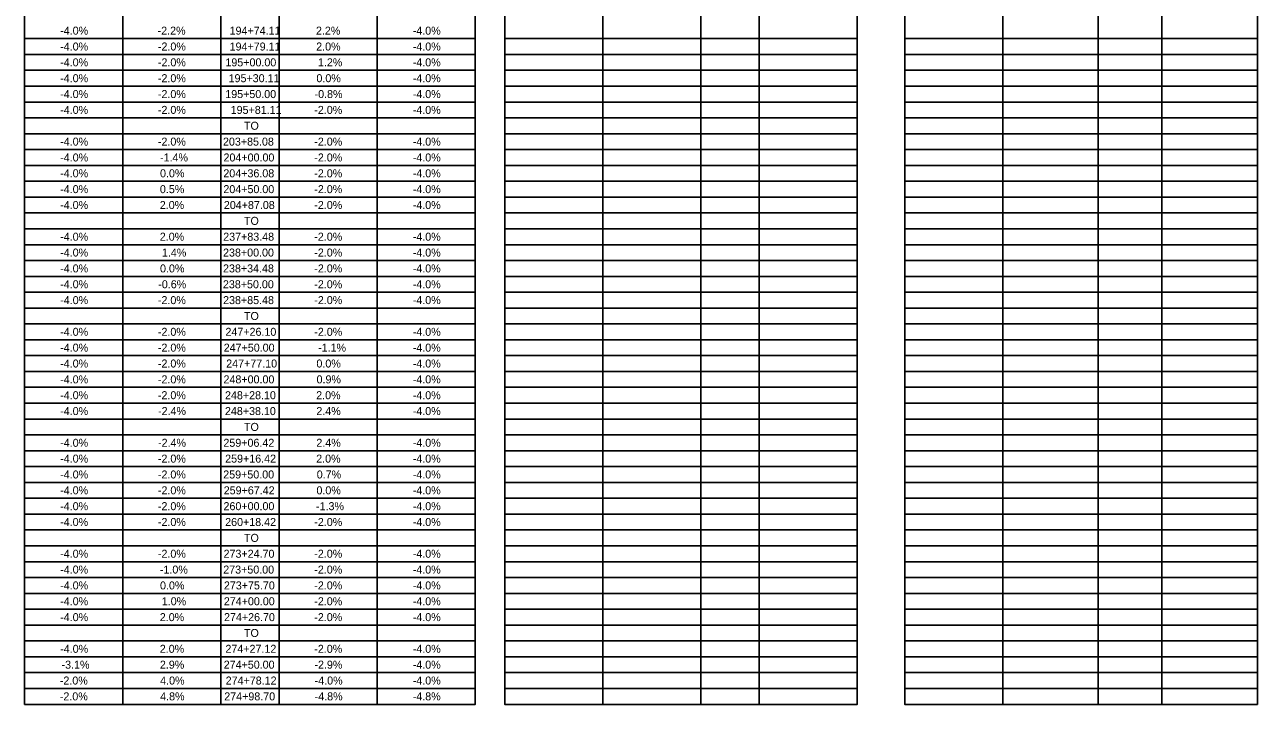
# Model space of a CAD drawing. Extents: x -15319374 to 1762012, y 465773 to 3693661.
# Drawn here: x -15317075.3 to -15316613.1, y 3692508 to 3692762.8 of the extents above; entities that cross this region are included whole.
import ezdxf

# ---------------------------------------------------------------- set-up
doc = ezdxf.new("R2010")
doc.units = 0
doc.layers.add('BORDER', color=7, linetype='Continuous')
doc.layers.add('DIMENSIONS', color=7, linetype='Continuous')

msp = doc.modelspace()

# ---------------------------------------------------------------- linework, layer by layer
at = {"layer": 'BORDER'}
for p, q in [((-15317038.55, 3693013.06), (-15317038.55, 3692507.99)), ((-15317001.78, 3693013.06), (-15317001.78, 3692507.99)), ((-15316979.91, 3693013.06), (-15316979.91, 3692507.99)), ((-15316943.14, 3693013.06), (-15316943.14, 3692507.99)), ((-15316858.55, 3693013.06), (-15316858.55, 3692507.99)), ((-15316821.78, 3693013.06), (-15316821.78, 3692507.99)), ((-15316799.91, 3693013.06), (-15316799.91, 3692507.99)), ((-15316708.55, 3693013.06), (-15316708.55, 3692507.99)), ((-15316672.78, 3693013.06), (-15316672.78, 3692507.99)), ((-15316648.91, 3693013.06), (-15316648.91, 3692507.99)), ((-15317075.32, 3692757.59), (-15316906.37, 3692757.59)), ((-15316895.32, 3692757.59), (-15316763.14, 3692757.59)), ((-15316745.32, 3692757.59), (-15316613.14, 3692757.59)), ((-15317075.32, 3692751.64), (-15316906.37, 3692751.64)), ((-15316895.32, 3692751.64), (-15316763.14, 3692751.64)), ((-15316745.32, 3692751.64), (-15316613.14, 3692751.64)), ((-15317075.32, 3692745.7), (-15316906.37, 3692745.7)), ((-15316895.32, 3692745.7), (-15316763.14, 3692745.7)), ((-15316745.32, 3692745.7), (-15316613.14, 3692745.7)), ((-15317075.32, 3692739.76), (-15316906.37, 3692739.76)), ((-15316895.32, 3692739.76), (-15316763.14, 3692739.76)), ((-15316745.32, 3692739.76), (-15316613.14, 3692739.76)), ((-15317075.32, 3692733.82), (-15316906.37, 3692733.82)), ((-15316895.32, 3692733.82), (-15316763.14, 3692733.82)), ((-15316745.32, 3692733.82), (-15316613.14, 3692733.82)), ((-15317075.32, 3692727.87), (-15316906.37, 3692727.87)), ((-15316895.32, 3692727.87), (-15316763.14, 3692727.87)), ((-15316745.32, 3692727.87), (-15316613.14, 3692727.87)), ((-15317075.32, 3692721.93), (-15316906.37, 3692721.93)), ((-15316895.32, 3692721.93), (-15316763.14, 3692721.93)), ((-15316745.32, 3692721.93), (-15316613.14, 3692721.93)), ((-15317075.32, 3692715.99), (-15316906.37, 3692715.99)), ((-15316895.32, 3692715.99), (-15316763.14, 3692715.99)), ((-15316745.32, 3692715.99), (-15316613.14, 3692715.99)), ((-15317075.32, 3692710.04), (-15316906.37, 3692710.04)), ((-15316895.32, 3692710.04), (-15316763.14, 3692710.04)), ((-15316745.32, 3692710.04), (-15316613.14, 3692710.04)), ((-15317075.32, 3692704.1), (-15316906.37, 3692704.1)), ((-15316895.32, 3692704.1), (-15316763.14, 3692704.1)), ((-15316745.32, 3692704.1), (-15316613.14, 3692704.1)), ((-15317075.32, 3692698.16), (-15316906.37, 3692698.16)), ((-15316895.32, 3692698.16), (-15316763.14, 3692698.16)), ((-15316745.32, 3692698.16), (-15316613.14, 3692698.16)), ((-15317075.32, 3692692.22), (-15316906.37, 3692692.22)), ((-15316895.32, 3692692.22), (-15316763.14, 3692692.22)), ((-15316745.32, 3692692.22), (-15316613.14, 3692692.22)), ((-15317075.32, 3692686.27), (-15316906.37, 3692686.27)), ((-15316895.32, 3692686.27), (-15316763.14, 3692686.27)), ((-15316745.32, 3692686.27), (-15316613.14, 3692686.27)), ((-15317075.32, 3692680.33), (-15316906.37, 3692680.33)), ((-15316895.32, 3692680.33), (-15316763.14, 3692680.33)), ((-15316745.32, 3692680.33), (-15316613.14, 3692680.33)), ((-15317075.32, 3692674.39), (-15316906.37, 3692674.39)), ((-15316895.32, 3692674.39), (-15316763.14, 3692674.39)), ((-15316745.32, 3692674.39), (-15316613.14, 3692674.39)), ((-15317075.32, 3692668.45), (-15316906.37, 3692668.45)), ((-15316895.32, 3692668.45), (-15316763.14, 3692668.45)), ((-15316745.32, 3692668.45), (-15316613.14, 3692668.45)), ((-15317075.32, 3692662.5), (-15316906.37, 3692662.5)), ((-15316895.32, 3692662.5), (-15316763.14, 3692662.5)), ((-15316745.32, 3692662.5), (-15316613.14, 3692662.5)), ((-15317075.32, 3692656.56), (-15316906.37, 3692656.56)), ((-15316895.32, 3692656.56), (-15316763.14, 3692656.56)), ((-15316745.32, 3692656.56), (-15316613.14, 3692656.56)), ((-15317075.32, 3692650.62), (-15316906.37, 3692650.62)), ((-15316895.32, 3692650.62), (-15316763.14, 3692650.62)), ((-15316745.32, 3692650.62), (-15316613.14, 3692650.62)), ((-15317075.32, 3692644.67), (-15316906.37, 3692644.67)), ((-15316895.32, 3692644.67), (-15316763.14, 3692644.67)), ((-15316745.32, 3692644.67), (-15316613.14, 3692644.67)), ((-15317075.32, 3692638.73), (-15316906.37, 3692638.73)), ((-15316895.32, 3692638.73), (-15316763.14, 3692638.73)), ((-15316745.32, 3692638.73), (-15316613.14, 3692638.73)), ((-15317075.32, 3692632.79), (-15316906.37, 3692632.79)), ((-15316895.32, 3692632.79), (-15316763.14, 3692632.79)), ((-15316745.32, 3692632.79), (-15316613.14, 3692632.79)), ((-15317075.32, 3692626.85), (-15316906.37, 3692626.85)), ((-15316895.32, 3692626.85), (-15316763.14, 3692626.85)), ((-15316745.32, 3692626.85), (-15316613.14, 3692626.85)), ((-15317075.32, 3692620.9), (-15316906.37, 3692620.9)), ((-15316895.32, 3692620.9), (-15316763.14, 3692620.9)), ((-15316745.32, 3692620.9), (-15316613.14, 3692620.9)), ((-15317075.32, 3692614.96), (-15316906.37, 3692614.96)), ((-15316895.32, 3692614.96), (-15316763.14, 3692614.96)), ((-15316745.32, 3692614.96), (-15316613.14, 3692614.96)), ((-15317075.32, 3692609.02), (-15316906.37, 3692609.02)), ((-15316895.32, 3692609.02), (-15316763.14, 3692609.02)), ((-15316745.32, 3692609.02), (-15316613.14, 3692609.02)), ((-15317075.32, 3692603.08), (-15316906.37, 3692603.08)), ((-15316895.32, 3692603.08), (-15316763.14, 3692603.08)), ((-15316745.32, 3692603.08), (-15316613.14, 3692603.08)), ((-15317075.32, 3692597.13), (-15316906.37, 3692597.13)), ((-15316895.32, 3692597.13), (-15316763.14, 3692597.13)), ((-15316745.32, 3692597.13), (-15316613.14, 3692597.13)), ((-15317075.32, 3692591.19), (-15316906.37, 3692591.19)), ((-15316895.32, 3692591.19), (-15316763.14, 3692591.19)), ((-15316745.32, 3692591.19), (-15316613.14, 3692591.19)), ((-15317075.32, 3692585.25), (-15316906.37, 3692585.25)), ((-15316895.32, 3692585.25), (-15316763.14, 3692585.25)), ((-15316745.32, 3692585.25), (-15316613.14, 3692585.25)), ((-15317075.32, 3692579.31), (-15316906.37, 3692579.31)), ((-15316895.32, 3692579.31), (-15316763.14, 3692579.31)), ((-15316745.32, 3692579.31), (-15316613.14, 3692579.31)), ((-15317075.32, 3692573.36), (-15316906.37, 3692573.36)), ((-15316895.32, 3692573.36), (-15316763.14, 3692573.36)), ((-15316745.32, 3692573.36), (-15316613.14, 3692573.36)), ((-15317075.32, 3692567.42), (-15316906.37, 3692567.42)), ((-15316895.32, 3692567.42), (-15316763.14, 3692567.42)), ((-15316745.32, 3692567.42), (-15316613.14, 3692567.42)), ((-15317075.32, 3692561.48), (-15316906.37, 3692561.48)), ((-15316895.32, 3692561.48), (-15316763.14, 3692561.48)), ((-15316745.32, 3692561.48), (-15316613.14, 3692561.48)), ((-15317075.32, 3692555.53), (-15316906.37, 3692555.53)), ((-15316895.32, 3692555.53), (-15316763.14, 3692555.53)), ((-15316745.32, 3692555.53), (-15316613.14, 3692555.53)), ((-15317075.32, 3692549.59), (-15316906.37, 3692549.59)), ((-15316895.32, 3692549.59), (-15316763.14, 3692549.59)), ((-15316745.32, 3692549.59), (-15316613.14, 3692549.59)), ((-15317075.32, 3692543.65), (-15316906.37, 3692543.65)), ((-15316895.32, 3692543.65), (-15316763.14, 3692543.65)), ((-15316745.32, 3692543.65), (-15316613.14, 3692543.65)), ((-15317075.32, 3692537.71), (-15316906.37, 3692537.71)), ((-15316895.32, 3692537.71), (-15316763.14, 3692537.71)), ((-15316745.32, 3692537.71), (-15316613.14, 3692537.71)), ((-15317075.32, 3692531.76), (-15316906.37, 3692531.76)), ((-15316895.32, 3692531.76), (-15316763.14, 3692531.76)), ((-15316745.32, 3692531.76), (-15316613.14, 3692531.76)), ((-15317075.32, 3692525.82), (-15316906.37, 3692525.82)), ((-15316895.32, 3692525.82), (-15316763.14, 3692525.82)), ((-15316745.32, 3692525.82), (-15316613.14, 3692525.82)), ((-15317075.32, 3692519.88), (-15316906.37, 3692519.88)), ((-15316895.32, 3692519.88), (-15316763.14, 3692519.88)), ((-15316745.32, 3692519.88), (-15316613.14, 3692519.88)), ((-15317075.32, 3692513.94), (-15316906.37, 3692513.94)), ((-15316895.32, 3692513.94), (-15316763.14, 3692513.94)), ((-15316745.32, 3692513.94), (-15316613.14, 3692513.94)), ((-15317075.32, 3692507.99), (-15316906.37, 3692507.99)), ((-15316745.32, 3692507.99), (-15316613.14, 3692507.99))]:
    msp.add_line(p, q, dxfattribs=at)
for points in [[(-15317075.32, 3693013.06), (-15316906.37, 3693013.06), (-15316906.37, 3692507.99), (-15317075.32, 3692507.99)], [(-15316895.32, 3693013.06), (-15316763.14, 3693013.06), (-15316763.14, 3692507.99), (-15316895.32, 3692507.99)], [(-15316745.32, 3693013.06), (-15316613.14, 3693013.06), (-15316613.14, 3692507.99), (-15316745.32, 3692507.99)]]:
    msp.add_lwpolyline(points, close=True, dxfattribs=at)
msp.add_lwpolyline([(-15317075.32, 3692507.99), (-15317075.32, 3693007.15), (-15316906.37, 3693007.15), (-15316906.37, 3692507.99)], dxfattribs=at)

# ---------------------------------------------------------------- texts
at = {"layer": 'DIMENSIONS'}
for s, p in [('-4.0%', (-15317061.99, 3692759.07)), ('-2.2%', (-15317025.46, 3692759.07)), ('194+74.11', (-15316998.47, 3692759.07)), ('2.2%', (-15316966.1, 3692759.07)), ('-4.0%', (-15316929.81, 3692759.07)), ('-4.0%', (-15317061.99, 3692753.13)), ('-2.0%', (-15317025.36, 3692753.13)), ('194+79.11', (-15316998.47, 3692753.13)), ('2.0%', (-15316966.01, 3692753.13)), ('-4.0%', (-15316929.81, 3692753.13)), ('-4.0%', (-15317061.99, 3692747.19)), ('-2.0%', (-15317025.36, 3692747.19)), ('195+00.00', (-15317000.05, 3692747.19)), ('1.2%', (-15316965.35, 3692747.19)), ('-4.0%', (-15316929.81, 3692747.19)), ('-4.0%', (-15317061.99, 3692741.25)), ('-2.0%', (-15317025.36, 3692741.25)), ('195+30.11', (-15316998.85, 3692741.25)), ('0.0%', (-15316965.92, 3692741.25)), ('-4.0%', (-15316929.81, 3692741.25)), ('-4.0%', (-15317061.99, 3692735.3)), ('-2.0%', (-15317025.36, 3692735.3)), ('195+50.00', (-15317000.1, 3692735.3)), ('-0.8%', (-15316966.62, 3692735.3)), ('-4.0%', (-15316929.81, 3692735.3)), ('-4.0%', (-15317061.99, 3692729.36)), ('-2.0%', (-15317025.36, 3692729.36)), ('195+81.11', (-15316998.07, 3692729.36)), ('-2.0%', (-15316966.72, 3692729.36)), ('-4.0%', (-15316929.81, 3692729.36)), ('TO', (-15316993.09, 3692723.42)), ('-4.0%', (-15317061.99, 3692717.47)), ('-2.0%', (-15317025.36, 3692717.47)), ('203+85.08', (-15317000.96, 3692717.47)), ('-2.0%', (-15316966.72, 3692717.47)), ('-4.0%', (-15316929.81, 3692717.47)), ('-4.0%', (-15317061.99, 3692711.53)), ('-1.4%', (-15317024.56, 3692711.53)), ('204+00.00', (-15317000.76, 3692711.53)), ('-2.0%', (-15316966.72, 3692711.53)), ('-4.0%', (-15316929.81, 3692711.53)), ('-4.0%', (-15317061.99, 3692705.59)), ('0.0%', (-15317024.56, 3692705.59)), ('204+36.08', (-15317000.82, 3692705.59)), ('-2.0%', (-15316966.72, 3692705.59)), ('-4.0%', (-15316929.81, 3692705.59)), ('-4.0%', (-15317061.99, 3692699.65)), ('0.5%', (-15317024.61, 3692699.65)), ('204+50.00', (-15317000.81, 3692699.65)), ('-2.0%', (-15316966.72, 3692699.65)), ('-4.0%', (-15316929.81, 3692699.65)), ('-4.0%', (-15317061.99, 3692693.7)), ('2.0%', (-15317024.65, 3692693.7)), ('204+87.08', (-15317000.63, 3692693.7)), ('-2.0%', (-15316966.72, 3692693.7)), ('-4.0%', (-15316929.81, 3692693.7)), ('TO', (-15316993.09, 3692687.76)), ('-4.0%', (-15317061.99, 3692681.82)), ('2.0%', (-15317024.65, 3692681.82)), ('237+83.48', (-15317000.87, 3692681.82)), ('-2.0%', (-15316966.72, 3692681.82)), ('-4.0%', (-15316929.81, 3692681.82)), ('-4.0%', (-15317061.99, 3692675.88)), ('1.4%', (-15317023.85, 3692675.88)), ('238+00.00', (-15317000.93, 3692675.88)), ('-2.0%', (-15316966.72, 3692675.88)), ('-4.0%', (-15316929.81, 3692675.88)), ('-4.0%', (-15317061.99, 3692669.93)), ('0.0%', (-15317024.56, 3692669.93)), ('238+34.48', (-15317000.94, 3692669.93)), ('-2.0%', (-15316966.72, 3692669.93)), ('-4.0%', (-15316929.81, 3692669.93)), ('-4.0%', (-15317061.99, 3692663.99)), ('-0.6%', (-15317025.22, 3692663.99)), ('238+50.00', (-15317000.98, 3692663.99)), ('-2.0%', (-15316966.72, 3692663.99)), ('-4.0%', (-15316929.81, 3692663.99)), ('-4.0%', (-15317061.99, 3692658.05)), ('-2.0%', (-15317025.36, 3692658.05)), ('238+85.48', (-15317000.92, 3692658.05)), ('-2.0%', (-15316966.72, 3692658.05)), ('-4.0%', (-15316929.81, 3692658.05)), ('TO', (-15316993.09, 3692652.1)), ('-4.0%', (-15317061.99, 3692646.16)), ('-2.0%', (-15317025.36, 3692646.16)), ('247+26.10', (-15317000.03, 3692646.16)), ('-2.0%', (-15316966.72, 3692646.16)), ('-4.0%', (-15316929.81, 3692646.16)), ('-4.0%', (-15317061.99, 3692640.22)), ('-2.0%', (-15317025.36, 3692640.22)), ('247+50.00', (-15317000.69, 3692640.22)), ('-1.1%', (-15316965.3, 3692640.22)), ('-4.0%', (-15316929.81, 3692640.22)), ('-4.0%', (-15317061.99, 3692634.28)), ('-2.0%', (-15317025.36, 3692634.28)), ('247+77.10', (-15316999.75, 3692634.28)), ('0.0%', (-15316965.92, 3692634.28)), ('-4.0%', (-15316929.81, 3692634.28)), ('-4.0%', (-15317061.99, 3692628.33)), ('-2.0%', (-15317025.36, 3692628.33)), ('248+00.00', (-15317000.76, 3692628.33)), ('0.9%', (-15316965.87, 3692628.33)), ('-4.0%', (-15316929.81, 3692628.33)), ('-4.0%', (-15317061.99, 3692622.39)), ('-2.0%', (-15317025.36, 3692622.39)), ('248+28.10', (-15317000.2, 3692622.39)), ('2.0%', (-15316966.01, 3692622.39)), ('-4.0%', (-15316929.81, 3692622.39)), ('-4.0%', (-15317061.99, 3692616.45)), ('-2.4%', (-15317025.31, 3692616.45)), ('248+38.10', (-15317000.22, 3692616.45)), ('2.4%', (-15316965.96, 3692616.45)), ('-4.0%', (-15316929.81, 3692616.45)), ('TO', (-15316993.09, 3692610.51)), ('-4.0%', (-15317061.99, 3692604.56)), ('-2.4%', (-15317025.31, 3692604.56)), ('259+06.42', (-15317000.8, 3692604.56)), ('2.4%', (-15316965.96, 3692604.56)), ('-4.0%', (-15316929.81, 3692604.56)), ('-4.0%', (-15317061.99, 3692598.62)), ('-2.0%', (-15317025.36, 3692598.62)), ('259+16.42', (-15317000.14, 3692598.62)), ('2.0%', (-15316966.01, 3692598.62)), ('-4.0%', (-15316929.81, 3692598.62)), ('-4.0%', (-15317061.99, 3692592.68)), ('-2.0%', (-15317025.36, 3692592.68)), ('259+50.00', (-15317000.86, 3692592.68)), ('0.7%', (-15316965.8, 3692592.68)), ('-4.0%', (-15316929.81, 3692592.68)), ('-4.0%', (-15317061.99, 3692586.73)), ('-2.0%', (-15317025.36, 3692586.73)), ('259+67.42', (-15317000.68, 3692586.73)), ('0.0%', (-15316965.92, 3692586.73)), ('-4.0%', (-15316929.81, 3692586.73)), ('-4.0%', (-15317061.99, 3692580.79)), ('-2.0%', (-15317025.36, 3692580.79)), ('260+00.00', (-15317000.76, 3692580.79)), ('-1.3%', (-15316966.08, 3692580.79)), ('-4.0%', (-15316929.81, 3692580.79)), ('-4.0%', (-15317061.99, 3692574.85)), ('-2.0%', (-15317025.36, 3692574.85)), ('260+18.42', (-15317000.14, 3692574.85)), ('-2.0%', (-15316966.72, 3692574.85)), ('-4.0%', (-15316929.81, 3692574.85)), ('TO', (-15316993.09, 3692568.91)), ('-4.0%', (-15317061.99, 3692562.96)), ('-2.0%', (-15317025.36, 3692562.96)), ('273+24.70', (-15317000.74, 3692562.96)), ('-2.0%', (-15316966.72, 3692562.96)), ('-4.0%', (-15316929.81, 3692562.96)), ('-4.0%', (-15317061.99, 3692557.02)), ('-1.0%', (-15317024.61, 3692557.02)), ('273+50.00', (-15317000.86, 3692557.02)), ('-2.0%', (-15316966.72, 3692557.02)), ('-4.0%', (-15316929.81, 3692557.02)), ('-4.0%', (-15317061.99, 3692551.08)), ('0.0%', (-15317024.56, 3692551.08)), ('273+75.70', (-15317000.62, 3692551.08)), ('-2.0%', (-15316966.72, 3692551.08)), ('-4.0%', (-15316929.81, 3692551.08)), ('-4.0%', (-15317061.99, 3692545.14)), ('1.0%', (-15317023.9, 3692545.14)), ('274+00.00', (-15317000.64, 3692545.14)), ('-2.0%', (-15316966.72, 3692545.14)), ('-4.0%', (-15316929.81, 3692545.14)), ('-4.0%', (-15317061.99, 3692539.19)), ('2.0%', (-15317024.65, 3692539.19)), ('274+26.70', (-15317000.57, 3692539.19)), ('-2.0%', (-15316966.72, 3692539.19)), ('-4.0%', (-15316929.81, 3692539.19)), ('TO', (-15316993.09, 3692533.25)), ('-4.0%', (-15317061.99, 3692527.31)), ('2.0%', (-15317024.65, 3692527.31)), ('274+27.12', (-15317000.04, 3692527.31)), ('-2.0%', (-15316966.72, 3692527.31)), ('-4.0%', (-15316929.81, 3692527.31)), ('-3.1%', (-15317061.49, 3692521.37)), ('2.9%', (-15317024.61, 3692521.37)), ('274+50.00', (-15317000.69, 3692521.37)), ('-2.9%', (-15316966.67, 3692521.37)), ('-4.0%', (-15316929.81, 3692521.37)), ('-2.0%', (-15317062.13, 3692515.42)), ('4.0%', (-15317024.51, 3692515.42)), ('274+78.12', (-15316999.95, 3692515.42)), ('-4.0%', (-15316966.58, 3692515.42)), ('-4.0%', (-15316929.81, 3692515.42)), ('-2.0%', (-15317062.13, 3692509.48)), ('4.8%', (-15317024.51, 3692509.48)), ('274+98.70', (-15317000.48, 3692509.48)), ('-4.8%', (-15316966.58, 3692509.48)), ('-4.8%', (-15316929.81, 3692509.48))]:
    msp.add_text(s, height=3, dxfattribs=at).set_placement(p)

doc.saveas('drawing.dxf')
